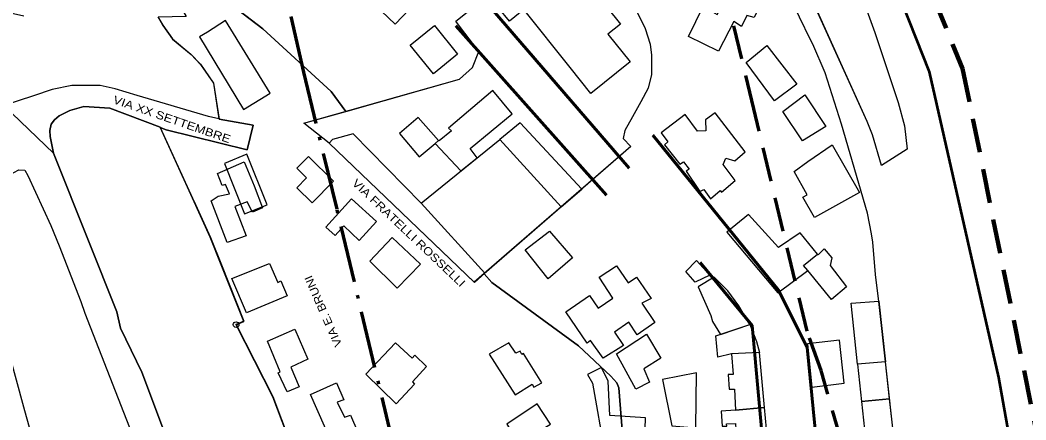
# Model space of a CAD drawing. Extents: x 654952 to 658955, y 890426 to 894481.
# Drawn here: x 657809.7 to 658161.5, y 891531.5 to 891671.6 of the extents above; entities that cross this region are included whole.
import ezdxf

# ---------------------------------------------------------------- set-up
doc = ezdxf.new("R2010")
doc.units = 0
doc.header["$LTSCALE"] = 4
doc.header["$PDMODE"] = 32
doc.header["$PDSIZE"] = 2
doc.linetypes.add('DOT_DASHED', pattern=[7.7, 5, -1.2, 0.3, -1.2])
doc.linetypes.add('MEDIUM_DASHED', pattern=[4.5, 3, -1.5])
for name, color, linetype, lineweight in [('1', 7, 'Continuous', 25), ('18', 7, 'Continuous', 25), ('4', 7, 'Continuous', 25), ('40', 7, 'Continuous', 60), ('45', 7, 'Continuous', 25), ('5', 7, 'Continuous', 25), ('55', 7, 'Continuous', 25), ('59', 7, 'Continuous', 53), ('6', 7, 'Continuous', 25), ('7', 7, 'MEDIUM_DASHED', 100), ('8', 7, 'Continuous', 25), ('9', 7, 'Continuous', 25)]:
    doc.layers.add(name, color=color, linetype=linetype, lineweight=lineweight)
doc.layers.add('58', color=7, linetype='Continuous')

msp = doc.modelspace()

# ---------------------------------------------------------------- linework, layer by layer
at = {"layer": '1'}
for points in [[(658097.01, 891635.16), (658091.3, 891653.07), (658086.95, 891663.09), (658086.17, 891664.7), (658078.45, 891680.69), (658070.24, 891698.33), (658056.42, 891725.44)], [(657866.54, 891675.07), (657867.75, 891672.76), (657857.94, 891672.62), (657859.6, 891669.67), (657862.98, 891664.85), (657869.49, 891659.51), (657872.79, 891656.04), (657877.31, 891649.49)], [(657877.31, 891649.49), (657879.27, 891636.92), (657891.18, 891634.76), (657889.07, 891626.08), (657860.82, 891633.15), (657858.69, 891633.98), (657869.97, 891609.21), (657871.01, 891606.93), (657876.26, 891595.41), (657880.07, 891585.84), (657887.92, 891566.07), (657885.22, 891564.91)], [(658144.06, 891484.59), (658142.62, 891520.35), (658114.79, 891519.13), (658114.78, 891523.44), (658115.29, 891525.52), (658110.08, 891573.06), (658108.87, 891582.51), (658107.91, 891593.79), (658107.5, 891596.67), (658106.07, 891603.96), (658097.01, 891635.16)], [(657885.22, 891564.91), (657898.05, 891539.74), (657909.85, 891508.4), (657924.5, 891474.4), (657928.08, 891465.62), (657953.49, 891476.31)]]:
    msp.add_lwpolyline(points, dxfattribs=at)
msp.add_point((657885.22, 891564.91), dxfattribs=at)
at = {"layer": '18'}
msp.add_lwpolyline([(658044.2, 891812.26), (658035.47, 891825.83), (658039.33, 891828.56), (658050.54, 891815.22), (658076.64, 891759.22), (658095.7, 891702.95), (658108.65, 891667.2), (658116.83, 891642.7), (658119.03, 891634.56), (658119.93, 891626.33), (658110.99, 891620.58), (658107.89, 891631.4), (658105.98, 891636), (658088.09, 891675.58)], dxfattribs=at)
at = {"layer": '4'}
for points in [[(657996.74, 891698.86), (658019.65, 891670.16), (658015.26, 891666.66), (658023.09, 891656.92), (658009.33, 891645.9), (658002.12, 891654.92), (657985.91, 891675.22), (657980.81, 891671.14), (657977, 891675.9), (657981.82, 891679.76), (657978.32, 891684.14)], [(657940.85, 891670.18), (657931.19, 891679.5), (657938.81, 891687.24), (657948.36, 891677.9)], [(658043.48, 891665.82), (658048.59, 891676.34), (658053.51, 891673.56), (658060.63, 891687.18), (658071.1, 891682.14), (658066.43, 891672.42), (658063.92, 891673.12), (658061.99, 891669.36), (658059.39, 891671.06), (658053.96, 891660.68)], [(657881.57, 891671.4), (657875.26, 891667.38), (657872.44, 891665.72), (657887.85, 891640.28), (657897.14, 891645.92)], [(657954.28, 891652.72), (657946.08, 891662.78), (657954.58, 891669.68), (657962.71, 891659.64)], [(658063.63, 891656.68), (658070.91, 891662.68), (658081.39, 891649.08), (658073.54, 891643.3)], [(657963.89, 891618.78), (657969.54, 891623.38), (657967.15, 891626.6), (657981.75, 891638.76), (657975.07, 891646.86), (657959.57, 891633.7), (657960.56, 891632.74), (657956.23, 891629.24), (657956.09, 891629.4), (657954.92, 891628.36)], [(658076.52, 891639.54), (658084.14, 891645.36), (658091.56, 891634.34), (658083.36, 891629.32)], [(657949.31, 891623.64), (657954.92, 891628.36), (657956.09, 891629.4), (657948.97, 891637.48), (657942.38, 891631.86)], [(658033.96, 891632.06), (658036.28, 891628.94), (658035.03, 891627.86), (658040.46, 891621.06), (658041.73, 891621.92), (658043.68, 891619.4), (658042.67, 891618.68), (658047.42, 891611.58), (658048.79, 891612.24), (658051.13, 891609), (658054.61, 891611.9), (658055.07, 891611.32), (658059.82, 891615.36), (658055.57, 891621), (658056.58, 891623.16), (658059.63, 891622.28), (658063.3, 891625.4), (658052.85, 891639.12), (658049.41, 891636.62), (658049.51, 891632.78), (658046.6, 891632.72), (658042.36, 891638.54)], [(657998.99, 891606.13), (658006.15, 891612.36), (657984.65, 891635.61), (657977.47, 891629.76)], [(657949.98, 891607.4), (657977.46, 891629.77), (657998.99, 891606.13), (657972.27, 891582.9)], [(658093.79, 891627.9), (658103.29, 891611.18), (658087.58, 891602.46), (658083.49, 891609.6), (658084.96, 891610.4), (658080.43, 891618.54), (658085.21, 891622.04)], [(657911.82, 891607.54), (657919.34, 891615.1), (657910.57, 891623.82), (657906.45, 891619.7), (657909.89, 891616.28), (657906.48, 891612.86)], [(657888.1, 891621.88), (657891.51, 891613.48), (657894.48, 891605.86), (657890.98, 891604.3), (657889.1, 891607.94), (657884.75, 891606.24), (657888.81, 891596.06), (657882.13, 891593.68), (657876.49, 891608.24), (657878.96, 891609.94), (657882.91, 891610.68), (657881.58, 891614), (657880.37, 891613.66), (657878.74, 891617.78)], [(657934.38, 891601), (657925.63, 891608.94), (657916.65, 891599.06), (657919.85, 891596.16), (657922.9, 891599.5), (657928.31, 891594.32)], [(658056.91, 891597.34), (658074.73, 891576.06), (658085.28, 891583.9), (658083.74, 891585.58), (658088.6, 891589.64), (658082.53, 891597), (658074.91, 891591.98), (658064.43, 891603.5)], [(657986.39, 891591.1), (657994.85, 891597.64), (658002.95, 891588.36), (657994.35, 891580.98)], [(657941.57, 891577.68), (657932.06, 891587.08), (657939.86, 891595.48), (657949.75, 891586.12)], [(658083.74, 891585.58), (658088.6, 891589.64), (658088.86, 891589.34), (658090.95, 891591.44), (658093.58, 891588.3), (658093.08, 891585.64), (658098.8, 891578.14), (658093.55, 891573.68), (658085.28, 891583.9)], [(658042.54, 891583.56), (658046.24, 891587.34), (658050.95, 891582.28), (658045.82, 891579.8)], [(657883.75, 891581.08), (657896.87, 891586.34), (657899.8, 891579.64), (657900.85, 891580.24), (657903.05, 891574.94), (657888.84, 891569.06)], [(658000.54, 891569.34), (658008.84, 891575.16), (658011.91, 891570.64), (658017.03, 891574.22), (658012.19, 891581.56), (658018.33, 891585.56), (658022.36, 891579.56), (658025.26, 891581.48), (658030.48, 891574.02), (658027.18, 891572.4), (658031.74, 891565.62), (658025.56, 891561.3), (658022.6, 891565.8), (658017.63, 891562.24), (658020.79, 891557.6), (658013.67, 891553.16), (658009.18, 891559.4), (658008.01, 891558.4)], [(658046.87, 891578.18), (658051.29, 891568.14), (658051.93, 891565.98), (658054.71, 891561.48), (658064.92, 891564.94), (658061.12, 891571.5), (658057.22, 891576.7), (658052.5, 891581.56)], [(658112.38, 891551.94), (658102.61, 891551.1), (658100.37, 891572.46), (658110.06, 891573.12)], [(657896.19, 891559.14), (657905.75, 891563.36), (657910.36, 891552.76), (657904.35, 891550.04), (657907.34, 891543.12), (657903.08, 891541.38), (657899.98, 891548.06), (657900.67, 891548.38)], [(658068.34, 891555.14), (658058.54, 891554.72), (658053.69, 891553.54), (658053.09, 891560.94), (658064.92, 891564.94), (658067.26, 891558.98)], [(658018.28, 891554.64), (658028.79, 891561.54), (658033.79, 891553.22), (658027.85, 891549.38), (658029.86, 891544.76), (658025.05, 891542.34)], [(658085.16, 891558.22), (658086.63, 891543.02), (658097.9, 891544.38), (658096.26, 891559.48)], [(657941.26, 891537.14), (657930.64, 891547.52), (657940.98, 891558.56), (657946.8, 891553.12), (657947.72, 891554.22), (657951.8, 891550.24), (657946.95, 891544.92), (657947.59, 891544.1)], [(657992.15, 891544.5), (657985.77, 891554.82), (657985.23, 891554.5), (657984.56, 891555.66), (657983.09, 891554.88), (657980.62, 891558.58), (657973.72, 891554.58), (657982.8, 891540.3), (657988.76, 891544.1), (657989.38, 891543.02)], [(658059.94, 891535), (658070.01, 891535.88), (658068.34, 891555.14), (658058.54, 891554.72), (658059.1, 891547.48), (658057.4, 891547.5), (658057.76, 891542.36), (658059.62, 891542.26)], [(658102.61, 891551.1), (658103.99, 891537.96), (658113.81, 891538.9), (658112.38, 891551.94)], [(658021.68, 891521.2), (658028.07, 891520.52), (658028.41, 891532.26), (658015.99, 891533.04), (658015.34, 891545.08), (658013.06, 891549.86), (658008.11, 891547.44), (658009.89, 891544.44), (658014.23, 891519.84), (658021.3, 891518.84)], [(658034.39, 891545.7), (658037.69, 891529.46), (658046.09, 891528.74), (658046.31, 891548.04)], [(657920.31, 891544.5), (657922.93, 891538.58), (657920.63, 891537.72), (657923.13, 891532.52), (657925.23, 891533.26), (657927.78, 891527.26), (657922.39, 891524.84), (657925.24, 891519.16), (657923.1, 891518.28), (657925.57, 891513.06), (657927.76, 891513.92), (657930.06, 891507.94), (657921.06, 891503.94), (657913.77, 891520.96), (657918.82, 891523.24), (657911.23, 891540.44)], [(658103.99, 891537.96), (658105.35, 891524.94), (658115.27, 891525.58), (658113.81, 891538.9)], [(657979.96, 891530.08), (657984.18, 891523.38), (657995.22, 891530.04), (657990.55, 891537.2)], [(658057.92, 891523.96), (658071.08, 891524.66), (658070.01, 891535.88), (658059.94, 891535), (658054.87, 891534.6), (658055.31, 891529.32), (658056.87, 891529.38), (658056.83, 891530.12), (658059.92, 891530.3), (658060.18, 891526.1), (658056.13, 891525.9), (658056.13, 891527.96), (658052.5, 891527.82), (658052.71, 891523.68)]]:
    msp.add_lwpolyline(points, close=True, dxfattribs=at)
for points in [[(657949.98, 891607.4), (657926.17, 891631.75), (657918.9, 891629.8), (657917.76, 891628.44), (657968.57, 891579.68)], [(657968.57, 891579.68), (657972.27, 891582.9), (657949.98, 891607.4)]]:
    msp.add_lwpolyline(points, dxfattribs=at)
at = {"layer": '40'}
for p, q in [((657972.08, 891678.4), (658022.77, 891619.71)), ((657962.05, 891669.55), (658014.81, 891610.28))]:
    msp.add_line(p, q, dxfattribs=at)
for points in [[(658111.19, 891273.19), (658100.58, 891384.08), (658092.91, 891475.8), (658084.96, 891556.9), (658074.93, 891576.95), (658031.01, 891631.21)], [(658047.53, 891586.68), (658065.8, 891564.56), (658072.58, 891488.48), (658078.76, 891414.16), (658085.24, 891320.08), (658094.09, 891213.92), (658080.24, 891159.95), (658043.39, 891102.74), (658023.06, 891083.86), (658008.02, 891082.68)]]:
    msp.add_lwpolyline(points, dxfattribs=at)
at = {"layer": '45', "linetype": 'DOT_DASHED', "lineweight": 70}
msp.add_lwpolyline([(658011.88, 891241.38), (657961.94, 891450.62), (657946.98, 891502.99), (657940.95, 891519.94), (657920.53, 891605.37), (657908.94, 891653.27), (657885.37, 891755.88), (657877.62, 891800.36), (657869.23, 891865.26), (657864.56, 891923.48), (657863.08, 891974.59), (657864.59, 892055.62), (657871.75, 892138.2), (657882.82, 892211.71), (657888.75, 892244.36), (657949.53, 892498.78)], dxfattribs=at)
at = {"layer": '45', "linetype": 'MEDIUM_DASHED', "lineweight": 70}
msp.add_lwpolyline([(658157.77, 891276.21), (658107.08, 891488.64), (658089.9, 891548.82), (658084.95, 891562.68), (658066.38, 891640.44), (658054.95, 891687.7), (658032.46, 891785.55), (658025.97, 891822.86), (658018.45, 891880.89), (658014.38, 891931.66), (658013.11, 891975.37), (658014.47, 892047.73), (658020.79, 892120.53), (658030.81, 892187.14), (658035.6, 892213.52), (658095.39, 892463.77)], dxfattribs=at)
at = {"layer": '5'}
msp.add_lwpolyline([(657830.83, 891467.72), (657829.01, 891473.58), (657823.72, 891491.98), (657818.84, 891508.15), (657814.86, 891522.18), (657811.39, 891534.78), (657805.15, 891557.48), (657792.14, 891573.58)], dxfattribs=at)
at = {"layer": '55'}
for points in [[(657700.14, 891897.46), (657705.26, 891883.93), (657717.21, 891866.25), (657732.05, 891837.27), (657738.79, 891819.16), (657750.86, 891823.91), (657764.66, 891785.1), (657769.46, 891786.57), (657777.47, 891786.24), (657780.57, 891781.45), (657770.43, 891768.16), (657805.8, 891739.98), (657812.04, 891747.32), (657821.03, 891740.63), (657850.06, 891702.07), (657875.51, 891683.22), (657894.62, 891668.46), (657918.52, 891646.58), (657923.57, 891639.6)], [(658165.52, 891469.7), (658151.87, 891546.37), (658127.68, 891653.47), (658089.83, 891749.07), (658069.36, 891782.29), (658056.07, 891803.35), (658076.64, 891759.22), (658095.7, 891702.95), (658108.65, 891667.2), (658116.83, 891642.7), (658119.03, 891634.56), (658119.93, 891626.33), (658110.99, 891620.58)], [(658110.99, 891620.58), (658107.89, 891631.4), (658105.98, 891636), (658080.67, 891692), (658066.01, 891721.68), (658056.23, 891743.9), (658060.14, 891747.27), (658057.32, 891753.32), (658050.21, 891747.17), (658047.26, 891744.62), (658030.86, 891732.87), (658019.53, 891724.25), (658015.79, 891720.41), (658006.09, 891710.81), (657990.74, 891724.73)], [(657923.57, 891639.6), (657963.43, 891650.91), (657967.92, 891654.99), (657970.16, 891660.52), (657963.38, 891669.4), (657962.14, 891671.2), (657996.74, 891698.86), (658000.93, 891705.64), (658008.3, 891698.88), (658010.85, 891692.3), (658021.54, 891680.2), (658023.61, 891677.78), (658026.27, 891672.98), (658028.35, 891668.56), (658030.02, 891663.18), (658030.56, 891659.24), (658030.52, 891652.46), (658029.34, 891647.74), (658026.85, 891642.96), (658023.91, 891637.66), (658021.22, 891632.9), (658020.6, 891630.06), (658023.3, 891627.34), (657971.97, 891582.71)], [(657923.57, 891639.6), (657918.52, 891646.58), (657894.62, 891668.46), (657877.23, 891681.89), (657866.54, 891675.07)], [(657866.54, 891675.07), (657867.75, 891672.76), (657857.94, 891672.62), (657859.6, 891669.67), (657862.98, 891664.85), (657869.49, 891659.51), (657872.79, 891656.04), (657877.31, 891649.49)], [(657877.31, 891649.49), (657879.27, 891636.92), (657891.18, 891634.76), (657889.07, 891626.08), (657860.82, 891633.15), (657858.69, 891633.98), (657869.97, 891609.21), (657871.01, 891606.93), (657876.26, 891595.41), (657880.07, 891585.84), (657887.92, 891566.07), (657885.22, 891564.91)], [(657971.97, 891582.71), (657968.55, 891579.74), (657917.74, 891628.5), (657908.97, 891635.46), (657923.57, 891639.6)], [(658043.93, 891277.75), (658041.09, 891309.92), (658032.66, 891400.94), (658027.98, 891444.55), (658023.37, 891488.38), (658019.17, 891542.72), (658018.38, 891544.51), (658016.35, 891546.87), (658005.05, 891557.44), (657974.69, 891579.7), (657971.97, 891582.71)], [(657971.97, 891582.71), (657974.69, 891579.7), (658005.05, 891557.44), (658016.35, 891546.87), (658018.38, 891544.51), (658019.17, 891542.72), (658023.37, 891488.38), (658027.98, 891444.55), (658032.66, 891400.94), (658041.09, 891309.92), (658050.36, 891204.78), (658064.96, 891168.92), (658095.53, 891144.7), (658099.62, 891134.92), (658103.55, 891127.27), (658126.17, 891072.18), (658137.14, 891047.22), (658141.29, 891031.32), (658156.84, 890999.94), (658167.45, 891016.27)], [(657885.22, 891564.91), (657898.05, 891539.74), (657909.85, 891508.4), (657924.5, 891474.4), (657928.08, 891465.62), (657953.49, 891476.31)]]:
    msp.add_lwpolyline(points, dxfattribs=at)
msp.add_point((657885.22, 891564.91), dxfattribs=at)
at = {"layer": '59'}
msp.add_lwpolyline([(658015.06, 892461.51), (657983.11, 892330.2), (657979.39, 892319.96), (657971.94, 892310.64), (657945.26, 892277.42), (657941.85, 892268.42), (657940.3, 892244.21), (657929.44, 892201.99), (657935.65, 892131.82), (657938.75, 892119.41), (657994.9, 891968.23), (658011.96, 891904.91), (658014.44, 891898.08), (658014.13, 891885.66), (658011.96, 891871.69), (658013.51, 891867.03), (658032.75, 891840.34), (658069.36, 891782.29), (658089.83, 891749.07), (658127.68, 891653.47), (658151.87, 891546.37), (658165.52, 891469.7)], dxfattribs=at)
at = {"layer": '6'}
msp.add_lwpolyline([(657881.15, 891621.39), (657888.2, 891603.75), (657896.09, 891606.9), (657889.04, 891624.55)], close=True, dxfattribs=at)
at = {"layer": '7'}
msp.add_lwpolyline([(658011.87, 892462.81), (657985.13, 892331.98), (657949.09, 892283.08), (657938.8, 892219.4), (657941.76, 892133.42), (658005.57, 891968.55), (658020.45, 891905.51), (658017.23, 891880.43), (658094.78, 891763.01), (658139.37, 891654.66), (658174.09, 891483.56)], dxfattribs=at)
at = {"layer": '8'}
msp.add_lwpolyline([(658026.27, 891672.98), (658028.35, 891668.56), (658030.02, 891663.18), (658030.56, 891659.24), (658030.52, 891652.46), (658029.34, 891647.74), (658026.85, 891642.96), (658023.91, 891637.66), (658021.22, 891632.9), (658020.6, 891630.06), (658023.3, 891627.34), (657968.55, 891579.74), (657917.74, 891628.5), (657908.97, 891635.46), (657963.43, 891650.91), (657967.92, 891654.99), (657970.16, 891660.52), (657963.38, 891669.4), (657962.14, 891671.2), (657996.74, 891698.86)], dxfattribs=at)
msp.add_lwpolyline([(658026.27, 891672.98), (658028.35, 891668.56), (658030.02, 891663.18), (658030.56, 891659.24), (658030.52, 891652.46), (658029.34, 891647.74), (658026.85, 891642.96), (658023.91, 891637.66), (658021.22, 891632.9), (658020.6, 891630.06), (658023.3, 891627.34), (657968.55, 891579.74), (657917.74, 891628.5), (657908.97, 891635.46), (657963.43, 891650.91), (657967.92, 891654.99), (657970.16, 891660.52), (657963.38, 891669.4), (657962.14, 891671.2), (657996.74, 891698.86)], dxfattribs=at)
at = {"layer": '9'}
msp.add_line((657803.95, 891641.7), (657821.32, 891624.99), dxfattribs=at)
for points in [[(657857.9, 891672.72), (657859.56, 891669.77), (657862.94, 891664.95), (657869.45, 891659.61), (657872.75, 891656.14), (657877.31, 891649.49), (657879.23, 891637.01), (657875.57, 891637.83), (657850.6, 891645.19), (657842.92, 891647.51), (657837.63, 891648.61), (657827.79, 891648.61), (657820.85, 891647.24), (657814.31, 891645.06), (657803.95, 891641.7), (657801.28, 891641.96), (657801.28, 891641.96), (657796.59, 891645.21), (657794.43, 891648.78), (657793.09, 891654.17), (657791.66, 891662.93), (657793.67, 891662.43), (657803.78, 891674.63), (657810.96, 891673.1)], [(657879.23, 891637.01), (657875.57, 891637.83), (657850.6, 891645.19), (657842.92, 891647.51), (657837.63, 891648.61), (657827.79, 891648.61), (657820.85, 891647.24), (657814.31, 891645.06), (657803.95, 891641.7)], [(657821.32, 891624.99), (657820.25, 891630.84), (657820.04, 891632.86), (657820.49, 891635.12), (657821.69, 891636.58), (657823.4, 891638.07), (657827.02, 891639.85), (657831.94, 891641.35), (657841.05, 891640.73), (657858.64, 891634.08), (657858.69, 891633.98), (657860.82, 891633.15), (657889.07, 891626.08), (657891.18, 891634.76)], [(657858.64, 891634.08), (657841.05, 891640.73), (657831.94, 891641.35), (657827.02, 891639.85), (657823.4, 891638.07), (657821.69, 891636.58), (657820.49, 891635.12), (657820.04, 891632.86), (657820.25, 891630.84), (657821.32, 891624.99), (657833.59, 891594.22)], [(657891.18, 891634.76), (657879.27, 891636.92), (657879.26, 891637.02), (657879.23, 891637.01)], [(657880.06, 891585.84), (657876.21, 891595.51), (657869.36, 891610.54), (657858.64, 891634.08)], [(657856.8, 891403.11), (657865.28, 891414.06), (657871.15, 891421.56), (657876, 891429.27), (657877.81, 891433.86), (657879.54, 891438.46), (657880.8, 891444.18), (657881.44, 891446.67), (657883.26, 891448.13), (657883.98, 891457.09), (657884.1, 891460.34), (657879.26, 891478.81), (657877.96, 891482.09), (657864.43, 891516.77), (657861.27, 891524.29), (657852.3, 891548.25), (657844.78, 891563.7), (657843.48, 891569.42), (657833.59, 891594.22), (657821.32, 891624.99)], [(657805.15, 891557.48), (657797.89, 891583.73), (657795.1, 891593.25), (657793.26, 891603.11), (657793.15, 891607.22), (657795.07, 891612.02), (657796.86, 891613.55), (657802.31, 891616.15), (657802.56, 891615.64), (657807.54, 891618.24), (657809.29, 891619.09), (657811.32, 891619), (657812.36, 891617.17), (657820.46, 891599.62), (657823.4, 891592.46), (657830.88, 891573.05), (657832.38, 891568.94), (657848.72, 891526.75), (657850.81, 891522.18), (657851.67, 891519.51), (657852.88, 891517.99)], [(657814.86, 891522.18), (657811.39, 891534.78), (657805.15, 891557.48), (657797.89, 891583.73), (657795.1, 891593.25), (657793.26, 891603.11), (657793.15, 891607.22), (657795.07, 891612.02), (657796.86, 891613.55), (657802.31, 891616.15), (657802.56, 891615.64), (657807.54, 891618.24), (657809.29, 891619.09), (657811.32, 891619), (657812.36, 891617.17), (657820.46, 891599.62), (657823.4, 891592.46), (657830.88, 891573.05), (657832.38, 891568.94), (657848.72, 891526.75)], [(657833.59, 891594.22), (657843.48, 891569.42), (657844.78, 891563.7), (657852.3, 891548.25), (657861.27, 891524.29), (657864.43, 891516.77), (657877.96, 891482.09), (657879.26, 891478.81), (657884.1, 891460.34), (657883.98, 891457.09), (657883.26, 891448.13)], [(657909.84, 891508.4), (657898.08, 891539.64), (657885.25, 891564.81), (657887.95, 891565.97), (657880.06, 891585.84)]]:
    msp.add_lwpolyline(points, dxfattribs=at)
msp.add_point((657885.22, 891564.91), dxfattribs=at)

# ---------------------------------------------------------------- texts
at = {"layer": '58'}
for s, height, rotation, width, p in [('VIA XX SETTEMBRE', 2.798, 340.933, 1.2, (657841.94, 891642.52)), ('VIA FRATELLI ROSSELLI', 2.802, 316.469, 1.2, (657925.56, 891614.17)), ('VIA E. BRUNI', 2.8, 113.776, 1.15, (657922.39, 891557.92))]:
    msp.add_text(s, height=height, rotation=rotation, dxfattribs=dict(at, width=width)).set_placement(p)

doc.saveas('drawing.dxf')
